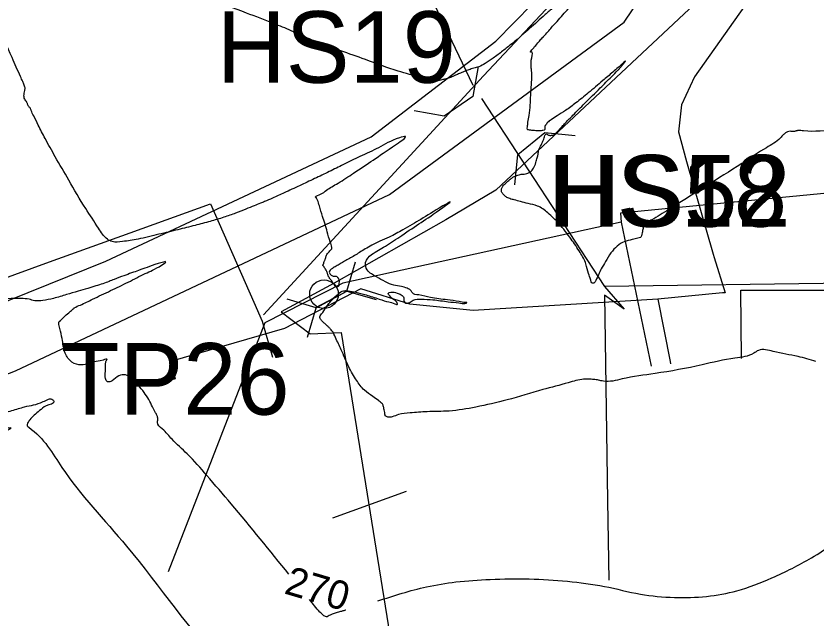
# Model space of a CAD drawing. Extents: x -478232 to -472707, y -1118753 to -1113967.
# Drawn here: x -475629.7 to -475517.8, y -1115586.5 to -1115502.2 of the extents above; entities that cross this region are included whole.
import ezdxf

# ---------------------------------------------------------------- set-up
doc = ezdxf.new("R2010")
doc.units = 0
for name, color, linetype in [('cesty', 7, 'Continuous'), ('el vedeni_NN', 7, 'Continuous'), ('hospodářské sjezdy', 7, 'Continuous'), ('ObPÚ', 7, 'Continuous'), ('plyn_ntl', 7, 'Continuous'), ('plyn_stl', 7, 'Continuous'), ('silnice', 7, 'Continuous'), ('telekomunikační kabel_O2', 7, 'Continuous'), ('TP_stavajicí_mosty', 7, 'Continuous'), ('VAK_vodovod_přípojky', 7, 'Continuous'), ('Vrstevnice_hlavni', 7, 'Continuous'), ('Vrstevnice_popis', 7, 'Continuous'), ('Vrstevnice_vedlejsi', 7, 'Continuous')]:
    doc.layers.add(name, color=color, linetype=linetype)

msp = doc.modelspace()

# ---------------------------------------------------------------- linework, layer by layer
at = {"layer": 'cesty'}
msp.add_circle((-475586.625, -1115541.102), 2, dxfattribs=at)
at = {"layer": 'el vedeni_NN'}
for points in [[(-475377.782, -1115185.638), (-475361.891, -1115178.13), (-475377.677, -1115209.214), (-475398.727, -1115246.374), (-475420.31, -1115282.665), (-475460.363, -1115351.777), (-475479.026, -1115383.225), (-475499.115, -1115417.348), (-475520.351, -1115454.7), (-475542.566, -1115487.377), (-475564.331, -1115510.556), (-475595.07, -1115543.98)], [(-475592.1, -1115463.897), (-475577.122, -1115488.137), (-475565.808, -1115511.875)], [(-475564.609, -1115513.741), (-475547.415, -1115540.02), (-475544.656, -1115543.188), (-475547.4, -1115541.22), (-475546.96, -1115569.997), (-475546.789, -1115581.094)], [(-475483.347, -1115539.435), (-475513.399, -1115539.58), (-475547.415, -1115540.02)], [(-475528.257, -1115550.101), (-475528.32, -1115540.56), (-475513.399, -1115540.56), (-475513.399, -1115539.58)]]:
    msp.add_lwpolyline(points, dxfattribs=at)
at = {"layer": 'hospodářské sjezdy'}
for p, q in [((-475565.048, -1115509.255), (-475565.813, -1115513.452)), ((-475565.813, -1115513.452), (-475569.829, -1115516.233)), ((-475569.829, -1115516.233), (-475574.026, -1115515.473)), ((-475559.527, -1115521.578), (-475555.747, -1115518.484)), ((-475555.747, -1115518.484), (-475551.502, -1115518.905)), ((-475559.953, -1115525.822), (-475559.527, -1115521.578))]:
    msp.add_line(p, q, dxfattribs=at)
at = {"layer": 'ObPÚ'}
for points in [[(-475728.43, -1115519.24), (-475712.42, -1115512.73), (-475696.58, -1115506.62), (-475678.04, -1115499.14), (-475661.39, -1115542.5), (-475657.48, -1115552.74), (-475617.15, -1115536.48), (-475580.03, -1115519.1), (-475562.62, -1115505.75), (-475549.77, -1115492.64), (-475525.8, -1115458.18), (-475508.23, -1115428.57), (-475505.83, -1115424.98), (-475499.16, -1115413.03), (-475489.23, -1115395.34), (-475521.11, -1115396.72), (-475521.1, -1115367.44), (-475509.54, -1115367.4), (-475488.54, -1115367.17), (-475472.37, -1115366.64), (-475447.91, -1115326.51)], [(-475448.49, -1115428.43), (-475454.53, -1115429.59), (-475463.73, -1115430.76), (-475472.79, -1115431.05), (-475479.94, -1115430.47), (-475488.06, -1115428.04), (-475488.8, -1115427.81), (-475491.24, -1115432.29), (-475508.31, -1115461.22), (-475522.38, -1115482.08), (-475534.81, -1115500.57), (-475562.61, -1115526.56), (-475569.57, -1115530.71), (-475585.22, -1115539.58), (-475592.62, -1115543.55), (-475588.56, -1115546.64), (-475584.24, -1115546.47), (-475575.51, -1115600.67), (-475574.56, -1115606.97), (-475568.59, -1115650.37), (-475601.06, -1115656.55), (-475624.46, -1115661.25), (-475654.25, -1115666.44)]]:
    msp.add_lwpolyline(points, dxfattribs=at)
at = {"layer": 'plyn_ntl'}
msp.add_line((-475585.38, -1115572.37), (-475575.07, -1115568.66), dxfattribs=at)
at = {"layer": 'plyn_stl'}
msp.add_lwpolyline([(-475699.229, -1115569.389), (-475682.71, -1115562.73), (-475680.94, -1115561.92), (-475675.76, -1115558.44), (-475667.15, -1115553.51), (-475655.03, -1115549.33), (-475634.75, -1115540.12), (-475625, -1115536.6), (-475613.74, -1115532.535), (-475602.48, -1115528.47), (-475596.433, -1115542.197), (-475595.26, -1115544.86), (-475593.843, -1115549.92)], dxfattribs=at)
at = {"layer": 'silnice'}
msp.add_lwpolyline([(-476261.922, -1115907.288), (-476203.622, -1115869.922), (-476022.083, -1115758.582), (-475811.314, -1115629.283), (-475771.826, -1115610.299), (-475706.185, -1115581.566), (-475629.775, -1115551.807), (-475577.467, -1115527.178), (-475544.647, -1115503.063), (-475523.184, -1115471.236), (-475482.102, -1115402.498), (-475367.21, -1115204.445), (-475326.334, -1115129.255), (-475275.418, -1115058.05)], dxfattribs=at)
at = {"layer": 'telekomunikační kabel_O2'}
for points in [[(-475520.23, -1115489.26), (-475526.49, -1115498.87), (-475534.82, -1115510.72), (-475536.63, -1115514.64), (-475537.05, -1115518.4), (-475535.94, -1115522.54), (-475532.21, -1115535.51)], [(-475532.21, -1115535.51), (-475532.08, -1115535.95), (-475530.51, -1115540.92), (-475530.9, -1115540.93)], [(-475539.93, -1115541.78), (-475565.75, -1115543.38), (-475574.63, -1115542.51), (-475581.49, -1115540.36), (-475592.14, -1115545.91), (-475608.07, -1115550.52)], [(-475530.9, -1115540.93), (-475539.93, -1115541.78)], [(-475539.93, -1115541.78), (-475538.22, -1115550.52), (-475538.15, -1115550.84)], [(-475608.07, -1115550.52), (-475607.42, -1115552.94)], [(-475607.42, -1115552.94), (-475607.9, -1115553.07)]]:
    msp.add_lwpolyline(points, dxfattribs=at)
at = {"layer": 'TP_stavajicí_mosty'}
for p, q in [((-475583.446, -1115540.671), (-475582.213, -1115536.588)), ((-475587.75, -1115542.982), (-475583.446, -1115540.671)), ((-475587.734, -1115543.012), (-475583.449, -1115540.666)), ((-475583.449, -1115540.666), (-475579.354, -1115541.86)), ((-475591.835, -1115541.754), (-475587.75, -1115542.982)), ((-475588.933, -1115547.106), (-475587.734, -1115543.012))]:
    msp.add_line(p, q, dxfattribs=at)
at = {"layer": 'VAK_vodovod_přípojky'}
for points in [[(-475400.788, -1115513.502), (-475400.524, -1115515.774), (-475545.153, -1115529.786), (-475545.079, -1115531.049), (-475540.879, -1115551.163)], [(-475545.079, -1115531.049), (-475583.983, -1115539.581), (-475594.886, -1115545.125), (-475608.399, -1115579.932)]]:
    msp.add_lwpolyline(points, dxfattribs=at)
at = {"layer": 'Vrstevnice_hlavni'}
for points in [[(-475591.524, -1115580.265), (-475599.609, -1115570.405), (-475603.006, -1115566.438), (-475605.756, -1115563.433), (-475607.86, -1115561.392), (-475609.247, -1115559.923), (-475609.92, -1115559.026), (-475609.876, -1115558.701), (-475609.874, -1115558.427), (-475609.913, -1115558.202), (-475609.993, -1115558.028), (-475610.223, -1115557.577), (-475610.602, -1115556.848), (-475611.13, -1115555.843), (-475611.784, -1115554.838), (-475612.563, -1115553.834), (-475613.468, -1115552.831), (-475614.385, -1115552.392), (-475615.315, -1115552.518), (-475616.257, -1115553.208), (-475616.885, -1115553.334), (-475617.199, -1115552.896), (-475617.199, -1115551.894), (-475617.188, -1115551.171), (-475617.165, -1115550.727), (-475617.132, -1115550.563), (-475617.087, -1115550.424), (-475617.03, -1115550.311), (-475616.962, -1115550.223), (-475617.522, -1115550.307), (-475618.71, -1115550.562), (-475620.526, -1115550.989), (-475621.889, -1115550.589), (-475622.798, -1115549.362), (-475623.254, -1115547.307), (-475623.56, -1115545.905), (-475623.717, -1115545.155), (-475623.725, -1115545.056), (-475623.491, -1115544.778), (-475623.016, -1115544.322), (-475622.3, -1115543.687), (-475621.816, -1115543.259), (-475621.564, -1115543.038), (-475621.544, -1115543.024), (-475620.687, -1115542.614), (-475618.993, -1115541.808), (-475616.462, -1115540.607), (-475614.01, -1115539.413), (-475611.639, -1115538.226), (-475609.348, -1115537.047), (-475608.735, -1115536.58), (-475609.8, -1115536.824), (-475612.543, -1115537.779), (-475614.606, -1115538.515), (-475615.988, -1115539.03), (-475616.689, -1115539.326), (-475617.534, -1115539.633), (-475618.524, -1115539.952), (-475619.658, -1115540.284), (-475621.024, -1115540.684), (-475622.622, -1115541.153), (-475624.451, -1115541.691), (-475625.936, -1115541.98), (-475627.075, -1115542.019), (-475627.87, -1115541.808), (-475628.975, -1115541.71), (-475630.391, -1115541.727), (-475632.117, -1115541.857), (-475633.269, -1115541.944), (-475633.845, -1115541.987), (-475633.846, -1115541.988), (-475633.935, -1115541.311), (-475634.111, -1115539.956), (-475634.376, -1115537.925), (-475634.629, -1115536.449), (-475634.872, -1115535.531), (-475635.105, -1115535.169), (-475636.099, -1115533.281), (-475637.853, -1115529.865), (-475640.368, -1115524.923), (-475642.128, -1115521.35), (-475643.132, -1115519.146), (-475643.38, -1115518.311), (-475643.745, -1115517.543), (-475644.228, -1115516.841), (-475644.827, -1115516.206), (-475645.294, -1115515.535), (-475645.627, -1115514.826), (-475645.827, -1115514.081), (-475646.265, -1115513.152), (-475646.941, -1115512.04), (-475647.855, -1115510.744), (-475648.331, -1115509.199), (-475648.37, -1115507.406), (-475647.972, -1115505.363), (-475647.723, -1115503.798), (-475647.624, -1115502.709)], [(-475579.109, -1115583.986), (-475572.285, -1115582.012), (-475568.185, -1115581.335), (-475563.397, -1115580.969), (-475557.92, -1115580.913), (-475552.593, -1115581.239), (-475547.416, -1115581.947), (-475542.388, -1115583.036), (-475537.622, -1115583.501), (-475533.118, -1115583.341), (-475528.876, -1115582.557), (-475523.989, -1115580.76), (-475518.456, -1115577.95), (-475512.277, -1115574.126), (-475511.964, -1115573.95)], [(-475583.591, -1115585.283), (-475583.637, -1115585.296), (-475583.865, -1115585.358), (-475584.299, -1115585.475), (-475584.938, -1115585.646), (-475585.465, -1115585.826), (-475585.881, -1115586.013), (-475586.186, -1115586.209), (-475586.627, -1115586.048), (-475587.204, -1115585.533), (-475588.634, -1115583.79)]]:
    msp.add_spline(points, degree=3, dxfattribs=at)
at = {"layer": 'Vrstevnice_vedlejsi'}
for points in [[(-475587.754, -1115527.573), (-475587.805, -1115527.556), (-475587.308, -1115527.218), (-475586.26, -1115526.559), (-475584.664, -1115525.578), (-475582.499, -1115524.177), (-475579.767, -1115522.355), (-475576.467, -1115520.112), (-475575.24, -1115519.076), (-475576.086, -1115519.248), (-475579.006, -1115520.626), (-475581.614, -1115521.871), (-475583.91, -1115522.984), (-475585.893, -1115523.964), (-475587.936, -1115524.948), (-475590.038, -1115525.937), (-475592.198, -1115526.931), (-475593.833, -1115527.671), (-475594.942, -1115528.158), (-475595.526, -1115528.392), (-475596.393, -1115528.74), (-475597.544, -1115529.202), (-475598.978, -1115529.777), (-475600.642, -1115530.35), (-475602.535, -1115530.92), (-475604.657, -1115531.486), (-475607.048, -1115532.09), (-475609.707, -1115532.73), (-475612.634, -1115533.406), (-475614.811, -1115533.747), (-475616.238, -1115533.753), (-475616.915, -1115533.424), (-475618.153, -1115531.882), (-475619.952, -1115529.128), (-475622.313, -1115525.162), (-475624.203, -1115521.896), (-475625.623, -1115519.329), (-475626.573, -1115517.462), (-475627.223, -1115516.164), (-475627.571, -1115515.436), (-475627.619, -1115515.276), (-475627.688, -1115515.129), (-475627.781, -1115514.995), (-475627.895, -1115514.873), (-475627.985, -1115514.745), (-475628.048, -1115514.609), (-475628.087, -1115514.467), (-475628.17, -1115514.289), (-475628.3, -1115514.076), (-475628.474, -1115513.828), (-475628.566, -1115513.533), (-475628.573, -1115513.19), (-475628.497, -1115512.799), (-475628.449, -1115512.5), (-475628.43, -1115512.292), (-475628.44, -1115512.175), (-475628.549, -1115511.868), (-475628.759, -1115511.372), (-475629.068, -1115510.687), (-475630.244, -1115508.031), (-475632.289, -1115503.403), (-475635.2, -1115496.804), (-475637.318, -1115492.11), (-475638.486, -1115489.639)], [(-475558.11, -1115517.06), (-475557.932, -1115516.133), (-475557.787, -1115514.622), (-475557.674, -1115512.527), (-475557.594, -1115509.849), (-475557.583, -1115508.082), (-475557.642, -1115507.228), (-475557.772, -1115507.286), (-475557.659, -1115507.093), (-475557.304, -1115506.649), (-475556.707, -1115505.954), (-475556.29, -1115505.472), (-475556.053, -1115505.205), (-475555.996, -1115505.151), (-475555.949, -1115505.107), (-475555.912, -1115505.072), (-475555.885, -1115505.046), (-475555.33, -1115504.422), (-475554.247, -1115503.201), (-475552.636, -1115501.382), (-475551.213, -1115499.67), (-475549.977, -1115498.066), (-475548.93, -1115496.57), (-475548.886, -1115496.153), (-475549.846, -1115496.815), (-475551.81, -1115498.555), (-475553.486, -1115500.044), (-475554.874, -1115501.282), (-475555.974, -1115502.268), (-475557.062, -1115503.241), (-475558.141, -1115504.199), (-475559.209, -1115505.143), (-475560.369, -1115506.11), (-475561.62, -1115507.099), (-475562.963, -1115508.111), (-475564.087, -1115508.85), (-475564.994, -1115509.316), (-475565.682, -1115509.509), (-475566.362, -1115509.731), (-475567.034, -1115509.982), (-475567.698, -1115510.262), (-475568.229, -1115510.491), (-475568.627, -1115510.669), (-475568.892, -1115510.797), (-475569.232, -1115510.916), (-475569.646, -1115511.028), (-475570.135, -1115511.133), (-475570.485, -1115511.213), (-475570.697, -1115511.269), (-475570.77, -1115511.3), (-475570.911, -1115511.342), (-475571.119, -1115511.394), (-475571.395, -1115511.457), (-475573.107, -1115510.961), (-475576.256, -1115509.908), (-475580.843, -1115508.297), (-475584.291, -1115507.072), (-475586.602, -1115506.234), (-475587.775, -1115505.781), (-475588.931, -1115505.305), (-475590.072, -1115504.804), (-475591.195, -1115504.279), (-475593.662, -1115503.278), (-475597.47, -1115501.8), (-475602.621, -1115499.845), (-475607.922, -1115497.397), (-475613.372, -1115494.456), (-475618.033, -1115491.609)], [(-475546.513, -1115535.309), (-475547.266, -1115536.546), (-475547.849, -1115537.569), (-475548.26, -1115538.376), (-475548.501, -1115538.969), (-475548.719, -1115539.366), (-475548.915, -1115539.566), (-475549.088, -1115539.57), (-475549.327, -1115539.123), (-475549.632, -1115538.226), (-475550.002, -1115536.878), (-475550.814, -1115535.267), (-475552.068, -1115533.392), (-475553.764, -1115531.254), (-475555.329, -1115529.716), (-475556.765, -1115528.778), (-475558.07, -1115528.441), (-475559.153, -1115528.157), (-475560.014, -1115527.926), (-475560.653, -1115527.748), (-475561.161, -1115527.498), (-475561.538, -1115527.177), (-475561.785, -1115526.785), (-475561.809, -1115526.387), (-475561.61, -1115525.984), (-475561.189, -1115525.576), (-475560.801, -1115525.224), (-475560.446, -1115524.931), (-475560.123, -1115524.694), (-475559.652, -1115524.499), (-475559.033, -1115524.344), (-475558.264, -1115524.231), (-475557.662, -1115523.886), (-475557.226, -1115523.31), (-475556.955, -1115522.504), (-475556.77, -1115521.885), (-475556.669, -1115521.455), (-475556.654, -1115521.213), (-475556.563, -1115520.897), (-475556.398, -1115520.505), (-475556.158, -1115520.039), (-475555.967, -1115519.62), (-475555.825, -1115519.246), (-475555.732, -1115518.92), (-475555.616, -1115518.74), (-475555.477, -1115518.708), (-475555.314, -1115518.823), (-475555.147, -1115518.891), (-475554.977, -1115518.912), (-475554.802, -1115518.886), (-475554.66, -1115518.864), (-475554.549, -1115518.847), (-475554.471, -1115518.833), (-475554.356, -1115518.754), (-475554.203, -1115518.611), (-475554.013, -1115518.402), (-475553.726, -1115518.089), (-475553.343, -1115517.672), (-475552.863, -1115517.151), (-475551.811, -1115516.075), (-475550.186, -1115514.443), (-475547.988, -1115512.256), (-475546.434, -1115510.705), (-475545.525, -1115509.788), (-475545.259, -1115509.506), (-475545.003, -1115509.213), (-475544.757, -1115508.909), (-475544.52, -1115508.595), (-475544.462, -1115508.482), (-475544.581, -1115508.57), (-475544.879, -1115508.86), (-475545.127, -1115509.095), (-475545.323, -1115509.276), (-475545.469, -1115509.402), (-475546.241, -1115510.061), (-475547.641, -1115511.252), (-475549.668, -1115512.974), (-475551.409, -1115514.366), (-475552.865, -1115515.426), (-475554.035, -1115516.154), (-475554.868, -1115516.712), (-475555.365, -1115517.1), (-475555.524, -1115517.318), (-475555.637, -1115517.471), (-475555.703, -1115517.561), (-475555.723, -1115517.587), (-475555.739, -1115517.681), (-475555.752, -1115517.842), (-475555.761, -1115518.07), (-475556.005, -1115518.213), (-475556.482, -1115518.268), (-475557.194, -1115518.238), (-475557.711, -1115518.193), (-475558.033, -1115518.133), (-475558.16, -1115518.06), (-475558.186, -1115517.702), (-475558.11, -1115517.06)], [(-475509.981, -1115518.054), (-475514.953, -1115518.181), (-475519.566, -1115518.277), (-475519.956, -1115518.242), (-475520.24, -1115518.227), (-475520.417, -1115518.233), (-475520.487, -1115518.259), (-475520.577, -1115518.285), (-475520.688, -1115518.311), (-475520.82, -1115518.337), (-475521.018, -1115518.351), (-475521.281, -1115518.35), (-475521.611, -1115518.336), (-475521.978, -1115518.484), (-475522.381, -1115518.795), (-475522.821, -1115519.268), (-475524.767, -1115520.622), (-475528, -1115522.718)], [(-475528, -1115522.718), (-475528.218, -1115522.855), (-475533.174, -1115525.967), (-475536.873, -1115528.287), (-475539.317, -1115529.813), (-475540.505, -1115530.545), (-475541.317, -1115531.036), (-475541.751, -1115531.286), (-475541.809, -1115531.294), (-475541.893, -1115531.503), (-475542.004, -1115531.912), (-475542.143, -1115532.523), (-475542.247, -1115532.934), (-475542.318, -1115533.146), (-475542.355, -1115533.159), (-475542.754, -1115533.267), (-475543.515, -1115533.471), (-475544.637, -1115533.772), (-475545.636, -1115534.384), (-475546.513, -1115535.309)], [(-475569.376, -1115541.9), (-475571.74, -1115541.553), (-475573.384, -1115541.215), (-475574.306, -1115540.885), (-475574.508, -1115540.562), (-475575.005, -1115540.279), (-475575.796, -1115540.034), (-475576.882, -1115539.827), (-475578.041, -1115539.373), (-475579.274, -1115538.669), (-475580.58, -1115537.718), (-475580.81, -1115536.684), (-475579.965, -1115535.57), (-475578.044, -1115534.374), (-475575.741, -1115532.876), (-475573.057, -1115531.077), (-475569.992, -1115528.977), (-475568.976, -1115528.205), (-475570.01, -1115528.761), (-475573.093, -1115530.645), (-475575.587, -1115532.098), (-475577.493, -1115533.12), (-475578.809, -1115533.711), (-475579.94, -1115534.265), (-475580.885, -1115534.781), (-475581.644, -1115535.26), (-475582.375, -1115535.706), (-475583.075, -1115536.12), (-475583.746, -1115536.502), (-475584.366, -1115536.857), (-475584.935, -1115537.187), (-475585.453, -1115537.49), (-475585.769, -1115537.765), (-475585.885, -1115538.013), (-475585.799, -1115538.233), (-475585.681, -1115538.399), (-475585.533, -1115538.51), (-475585.353, -1115538.566), (-475585.198, -1115538.596), (-475585.069, -1115538.601), (-475584.966, -1115538.581), (-475584.85, -1115538.631), (-475584.723, -1115538.749), (-475584.584, -1115538.937), (-475584.521, -1115539.209), (-475584.536, -1115539.565), (-475584.628, -1115540.004), (-475584.835, -1115540.089), (-475585.156, -1115539.82), (-475585.592, -1115539.196), (-475585.885, -1115538.778), (-475586.035, -1115538.565), (-475586.042, -1115538.559), (-475586.049, -1115538.539), (-475586.056, -1115538.505), (-475586.064, -1115538.458), (-475586.095, -1115538.349), (-475586.151, -1115538.18), (-475586.23, -1115537.951), (-475586.335, -1115537.728), (-475586.464, -1115537.512), (-475586.618, -1115537.301), (-475586.721, -1115537.154), (-475586.775, -1115537.071), (-475586.779, -1115537.052), (-475586.767, -1115537.018), (-475586.737, -1115536.97), (-475586.691, -1115536.908), (-475586.663, -1115536.849), (-475586.654, -1115536.791), (-475586.664, -1115536.735), (-475586.644, -1115536.646), (-475586.594, -1115536.523), (-475586.514, -1115536.366), (-475586.442, -1115536.189), (-475586.38, -1115535.992), (-475586.326, -1115535.775), (-475586.21, -1115535.544), (-475586.031, -1115535.299), (-475585.789, -1115535.04), (-475585.626, -1115534.862), (-475585.541, -1115534.765), (-475585.535, -1115534.748), (-475585.529, -1115534.735), (-475585.525, -1115534.723), (-475585.522, -1115534.715), (-475585.522, -1115534.684), (-475585.524, -1115534.632), (-475585.528, -1115534.557), (-475585.745, -1115533.801), (-475586.174, -1115532.362), (-475586.816, -1115530.242), (-475587.27, -1115528.769), (-475587.539, -1115527.944), (-475587.62, -1115527.766), (-475587.692, -1115527.643), (-475587.754, -1115527.573)], [(-475517.828, -1115550.496), (-475520.343, -1115549.824), (-475523.811, -1115549.108), (-475525.873, -1115548.952), (-475526.527, -1115549.357), (-475529.155, -1115550.032), (-475533.756, -1115550.978), (-475540.329, -1115552.193), (-475544.932, -1115552.956), (-475547.563, -1115553.265), (-475548.222, -1115553.122), (-475548.901, -1115553.03), (-475549.6, -1115552.987), (-475550.319, -1115552.994), (-475552.462, -1115553.481), (-475556.029, -1115554.446), (-475561.022, -1115555.89), (-475565.385, -1115556.886), (-475569.118, -1115557.432), (-475572.222, -1115557.53), (-475574.585, -1115557.697), (-475576.205, -1115557.934), (-475577.084, -1115558.241), (-475577.699, -1115558.294), (-475578.049, -1115558.095), (-475578.134, -1115557.644), (-475578.21, -1115557.261), (-475578.276, -1115556.949), (-475578.332, -1115556.706), (-475578.399, -1115556.52), (-475578.478, -1115556.391), (-475578.568, -1115556.319), (-475579.012, -1115555.983), (-475579.812, -1115555.383), (-475580.966, -1115554.517), (-475582.085, -1115553.143), (-475583.17, -1115551.258), (-475584.22, -1115548.865), (-475585.001, -1115547.179), (-475585.513, -1115546.202), (-475585.758, -1115545.932), (-475586.036, -1115545.652), (-475586.348, -1115545.361), (-475586.694, -1115545.06), (-475586.954, -1115544.797), (-475587.129, -1115544.571), (-475587.218, -1115544.383), (-475586.968, -1115543.863), (-475586.378, -1115543.01), (-475585.448, -1115541.825), (-475584.614, -1115541.034), (-475583.877, -1115540.637), (-475583.236, -1115540.633), (-475582.192, -1115540.822), (-475580.747, -1115541.205), (-475578.899, -1115541.781), (-475577.553, -1115542.19), (-475576.708, -1115542.434), (-475576.364, -1115542.511), (-475576.372, -1115542.352), (-475576.731, -1115541.958), (-475577.442, -1115541.327), (-475577.627, -1115540.948), (-475577.285, -1115540.821), (-475576.417, -1115540.945), (-475575.814, -1115541.202), (-475575.478, -1115541.591), (-475575.407, -1115542.113), (-475575.16, -1115542.347), (-475574.738, -1115542.292), (-475574.14, -1115541.947), (-475573.027, -1115541.811), (-475571.398, -1115541.882), (-475569.254, -1115542.16), (-475567.762, -1115542.329), (-475566.921, -1115542.387), (-475566.731, -1115542.336), (-475566.657, -1115542.297), (-475566.698, -1115542.271), (-475566.855, -1115542.258), (-475567.747, -1115542.135), (-475569.376, -1115541.9)], [(-475644.775, -1115561.525), (-475644.553, -1115561.716), (-475644.419, -1115561.902), (-475644.372, -1115562.084), (-475644.413, -1115562.261), (-475644.488, -1115562.402), (-475644.597, -1115562.509), (-475644.741, -1115562.58), (-475644.643, -1115562.97), (-475644.303, -1115563.677), (-475643.722, -1115564.701), (-475643.33, -1115565.387), (-475643.125, -1115565.735), (-475643.108, -1115565.744), (-475643.062, -1115565.734), (-475642.987, -1115565.704), (-475642.884, -1115565.655), (-475641.418, -1115564.977), (-475638.589, -1115563.669), (-475634.397, -1115561.731), (-475631.683, -1115560.443), (-475630.448, -1115559.803), (-475630.69, -1115559.813), (-475630.89, -1115559.744), (-475631.046, -1115559.596), (-475631.16, -1115559.37), (-475631.274, -1115559.148), (-475631.391, -1115558.93), (-475631.51, -1115558.715), (-475631.587, -1115558.507), (-475631.624, -1115558.305), (-475631.62, -1115558.109), (-475631.557, -1115557.94), (-475631.434, -1115557.799), (-475631.252, -1115557.684), (-475630.269, -1115557.367), (-475628.485, -1115556.848), (-475625.901, -1115556.127), (-475624.539, -1115555.867), (-475624.397, -1115556.068), (-475625.476, -1115556.729), (-475626.393, -1115557.382), (-475627.149, -1115558.024), (-475627.742, -1115558.658), (-475628.066, -1115559.149), (-475628.122, -1115559.498), (-475627.91, -1115559.704), (-475623.276, -1115565.32), (-475614.22, -1115576.346), (-475600.742, -1115592.782), (-475591.753, -1115603.737), (-475587.254, -1115609.211), (-475587.245, -1115609.205), (-475587.232, -1115609.199), (-475587.215, -1115609.194), (-475587.195, -1115609.188), (-475587.13, -1115609.17), (-475587.02, -1115609.138), (-475586.864, -1115609.093), (-475583.35, -1115609.028), (-475576.475, -1115608.944), (-475566.24, -1115608.839), (-475556.285, -1115609.448), (-475546.609, -1115610.771), (-475537.213, -1115612.807), (-475530.312, -1115614.046), (-475528.152, -1115614.336)], [(-475811.843, -1115589.098), (-475806.668, -1115588.433), (-475802.959, -1115587.87), (-475800.717, -1115587.407), (-475799.941, -1115587.045), (-475798.521, -1115586.629), (-475796.458, -1115586.16), (-475793.75, -1115585.638), (-475790.96, -1115585.804), (-475788.087, -1115586.66), (-475785.131, -1115588.204), (-475782.737, -1115589.574), (-475780.904, -1115590.769), (-475779.633, -1115591.79), (-475777.973, -1115592.489), (-475775.924, -1115592.864), (-475773.485, -1115592.916), (-475767.267, -1115594.67), (-475757.27, -1115598.125), (-475743.493, -1115603.281), (-475733.601, -1115607.294), (-475727.593, -1115610.164), (-475725.471, -1115611.89), (-475723.13, -1115612.984), (-475720.569, -1115613.444), (-475717.788, -1115613.272), (-475715.213, -1115613.282), (-475712.844, -1115613.475), (-475710.68, -1115613.85), (-475709.072, -1115614.206), (-475708.019, -1115614.545), (-475707.523, -1115614.865), (-475706.707, -1115615.319), (-475705.572, -1115615.908), (-475704.116, -1115616.63), (-475698.148, -1115618.585), (-475687.667, -1115621.772), (-475672.674, -1115626.19), (-475662.363, -1115629.476), (-475656.736, -1115631.63), (-475655.792, -1115632.652), (-475654.354, -1115633.953), (-475652.421, -1115635.534), (-475649.994, -1115637.394), (-475648.293, -1115638.659), (-475647.317, -1115639.328), (-475647.067, -1115639.402), (-475646.579, -1115639.624), (-475645.853, -1115639.994), (-475644.888, -1115640.511), (-475643.837, -1115641.049), (-475642.7, -1115641.606), (-475641.477, -1115642.184), (-475640.547, -1115642.576), (-475639.911, -1115642.782), (-475639.569, -1115642.802), (-475638.286, -1115643.971), (-475636.063, -1115646.289), (-475632.9, -1115649.755), (-475630.403, -1115652.368), (-475628.572, -1115654.126), (-475627.408, -1115655.03), (-475626.263, -1115655.851), (-475625.136, -1115656.588), (-475624.027, -1115657.241), (-475623.122, -1115657.91), (-475622.421, -1115658.597), (-475621.923, -1115659.301), (-475621.576, -1115659.828), (-475621.379, -1115660.18), (-475621.333, -1115660.356), (-475621.215, -1115660.503), (-475621.024, -1115660.621), (-475620.761, -1115660.71), (-475620.54, -1115660.782), (-475620.362, -1115660.836), (-475620.225, -1115660.873), (-475619.903, -1115660.963), (-475619.394, -1115661.104), (-475618.699, -1115661.296), (-475618.02, -1115661.581), (-475617.356, -1115661.956), (-475616.706, -1115662.423), (-475616.078, -1115662.701), (-475615.47, -1115662.79), (-475614.884, -1115662.691), (-475614.427, -1115662.633), (-475614.101, -1115662.615), (-475613.905, -1115662.638), (-475613.615, -1115662.702), (-475613.229, -1115662.808), (-475612.749, -1115662.956), (-475611.641, -1115663.191), (-475609.905, -1115663.514), (-475607.54, -1115663.924), (-475605.647, -1115664.255), (-475604.226, -1115664.508)]]:
    msp.add_spline(points, degree=3, dxfattribs=at)

# ---------------------------------------------------------------- texts
at = {"layer": 'hospodářské sjezdy'}
for s, p in [('HS19', (-475601.627, -1115511.544)), ('HS18', (-475555.326, -1115531.661)), ('HS52', (-475554.849, -1115531.661))]:
    msp.add_text(s, height=10, rotation=359.99999, dxfattribs=at).set_placement(p)
at = {"layer": 'TP_stavajicí_mosty'}
msp.add_text('TP26', height=10, rotation=359.99999, dxfattribs=at).set_placement((-475623.402, -1115557.94))
at = {"layer": 'Vrstevnice_popis'}
msp.add_text(' 270 ', height=4, rotation=343.50155, dxfattribs=at).set_placement((-475593.767, -1115582.478))

doc.saveas('drawing.dxf')
